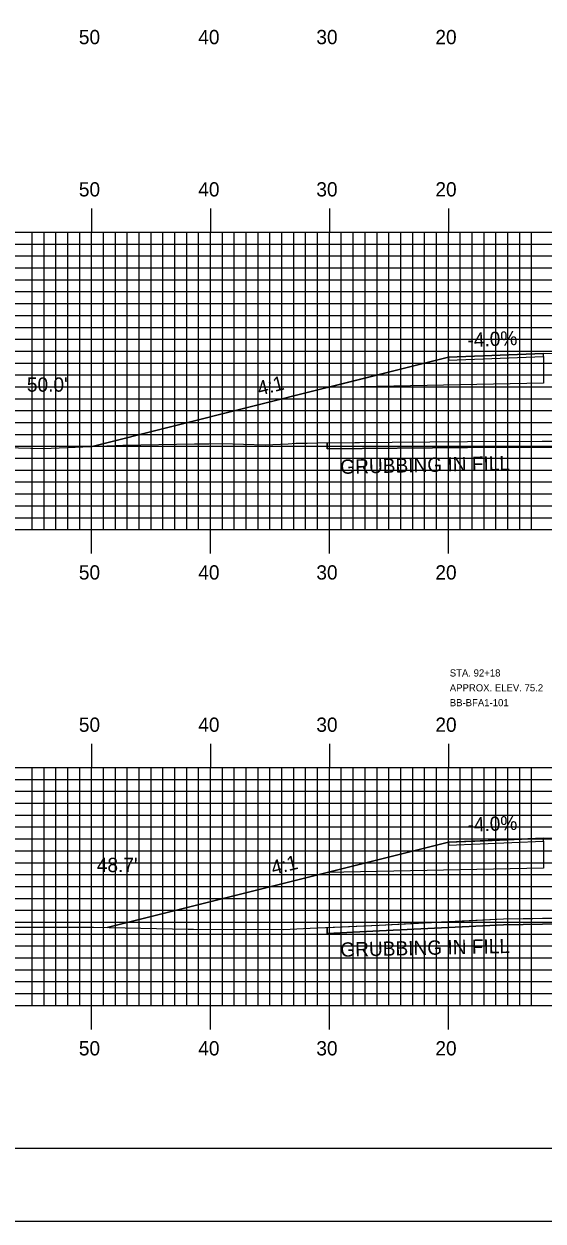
# Model space of a CAD drawing. Extents: x 1764939 to 1765282, y 442591 to 442811.
# Drawn here: x 1765049.2 to 1765092.8, y 442590.5 to 442691.2 of the extents above; entities that cross this region are included whole.
import ezdxf

# ---------------------------------------------------------------- set-up
doc = ezdxf.new("R2010")
doc.units = 0
for name, color, linetype in [('ANNOTATION', 7, 'Continuous'), ('BORDER', 7, 'Continuous'), ('D_Roadway_Centerline', 7, 'Continuous'), ('D_Roadway_Edge_Shoulder', 7, 'Continuous'), ('D_Roadway_SlopeLines', 7, 'Continuous'), ('D_Roadway_SubGrade', 7, 'Continuous'), ('D_Text_Standard', 7, 'Continuous'), ('GRUBBING IN FILL', 7, 'Continuous'), ('H_V ANNOTATION', 7, 'Continuous'), ('MAJOR', 7, 'Continuous'), ('MINOR', 7, 'Continuous'), ('PLOT BOUNDARY', 7, 'Continuous'), ('ROCKS', 7, 'Continuous'), ('S_Roadway_Centerline', 7, 'Continuous')]:
    doc.layers.add(name, color=color, linetype=linetype)

msp = doc.modelspace()

# ---------------------------------------------------------------- linework, layer by layer
at = {"layer": 'BORDER'}
msp.add_lwpolyline([(1764955.26, 442596.67), (1765275.26, 442596.67), (1765275.26, 442806.67), (1764955.26, 442806.67)], close=True, dxfattribs=at)
at = {"layer": 'D_Roadway_Centerline'}
for points in [[(1765054.9, 442655.66), (1765074.68, 442660.6), (1765074.68, 442660.6), (1765074.69, 442660.6), (1765084.86, 442663.15), (1765092.86, 442663.47), (1765092.86, 442663.47), (1765098.25, 442663.57), (1765104.85, 442663.71), (1765104.86, 442663.71), (1765116.85, 442663.47), (1765116.86, 442663.47), (1765116.86, 442663.47), (1765124.86, 442663.15), (1765124.86, 442663.15), (1765135.03, 442660.6), (1765136.03, 442660.35), (1765136.86, 442660.15), (1765151.59, 442656.46), (1765151.59, 442656.46)], [(1765056.16, 442615.22), (1765056.16, 442615.22), (1765074.68, 442619.85), (1765074.69, 442619.85), (1765079.22, 442620.99), (1765084.86, 442622.4), (1765084.86, 442622.4), (1765088.54, 442622.54), (1765092.86, 442622.72), (1765092.86, 442622.72), (1765104.86, 442622.96), (1765104.86, 442622.96), (1765116.86, 442622.72), (1765116.86, 442622.72), (1765122.81, 442622.48), (1765124.86, 442622.4), (1765124.86, 442622.4), (1765135.03, 442619.85), (1765135.03, 442619.85), (1765136.86, 442619.4), (1765136.86, 442619.4), (1765148.63, 442616.45)]]:
    msp.add_lwpolyline(points, dxfattribs=at)
at = {"layer": 'D_Roadway_Edge_Shoulder'}
for points in [[(1765092.86, 442663.47), (1765084.86, 442663.15), (1765084.86, 442662.9), (1765092.86, 442663.22)], [(1765092.86, 442622.72), (1765084.86, 442622.4), (1765084.86, 442622.15), (1765092.86, 442622.47)]]:
    msp.add_lwpolyline(points, close=True, dxfattribs=at)
at = {"layer": 'D_Roadway_SlopeLines'}
for points in [[(1765084.86, 442663.15), (1765074.68, 442660.6), (1765054.9, 442655.66)], [(1765084.86, 442622.4), (1765074.68, 442619.85), (1765056.16, 442615.22)]]:
    msp.add_lwpolyline(points, dxfattribs=at)
at = {"layer": 'D_Roadway_SubGrade'}
for points in [[(1765084.86, 442662.9), (1765092.86, 442663.22), (1765092.86, 442662.8), (1765092.86, 442660.97), (1765074.68, 442660.6), (1765084.86, 442663.15)], [(1765084.86, 442622.15), (1765092.86, 442622.47), (1765092.86, 442622.05), (1765092.86, 442620.22), (1765074.68, 442619.85), (1765084.86, 442622.4)]]:
    msp.add_lwpolyline(points, close=True, dxfattribs=at)
at = {"layer": 'GRUBBING IN FILL'}
for p, q in [((1765074.68, 442655.95), (1765074.68, 442655.45)), ((1765074.68, 442615.23), (1765074.68, 442614.73))]:
    msp.add_line(p, q, dxfattribs=at)
for points in [[(1765074.68, 442655.45), (1765074.68, 442655.95), (1765080.14, 442656.01), (1765086.46, 442656.07), (1765092.75, 442656.09), (1765099.04, 442656.11), (1765104.86, 442656.13), (1765104.86, 442655.63), (1765101.88, 442655.62), (1765099.04, 442655.61), (1765092.75, 442655.59), (1765086.46, 442655.57), (1765080.57, 442655.51)], [(1765074.68, 442655.45), (1765074.68, 442655.95), (1765080.14, 442656.01), (1765086.46, 442656.07), (1765092.75, 442656.09), (1765099.04, 442656.11), (1765104.86, 442656.13), (1765104.86, 442655.63), (1765101.88, 442655.62), (1765099.04, 442655.61), (1765092.75, 442655.59), (1765086.46, 442655.57), (1765080.57, 442655.51)], [(1765074.68, 442615.23), (1765079.04, 442615.43), (1765084.27, 442615.69), (1765089.49, 442615.94), (1765094.43, 442616.02), (1765099.36, 442616.11), (1765104, 442616.29), (1765104.86, 442616.32), (1765104.86, 442615.82), (1765104.01, 442615.79), (1765099.37, 442615.61), (1765094.44, 442615.53), (1765089.51, 442615.44), (1765084.29, 442615.19), (1765079.07, 442614.93), (1765074.68, 442614.73)], [(1765074.68, 442615.23), (1765079.04, 442615.43), (1765084.27, 442615.69), (1765089.49, 442615.94), (1765094.43, 442616.02), (1765099.36, 442616.11), (1765104, 442616.29), (1765104.86, 442616.32), (1765104.86, 442615.82), (1765104.01, 442615.79), (1765099.37, 442615.61), (1765094.44, 442615.53), (1765089.51, 442615.44), (1765084.29, 442615.19), (1765079.07, 442614.93), (1765074.68, 442614.73)]]:
    msp.add_lwpolyline(points, close=True, dxfattribs=at)
for points in [[(1765074.68, 442655.45), (1765086.46, 442655.57), (1765099.04, 442655.61), (1765104.73, 442655.63), (1765111.86, 442655.7), (1765122.5, 442655.9), (1765131.78, 442655.91), (1765135.03, 442655.92)], [(1765074.68, 442614.73), (1765079.07, 442614.93), (1765089.51, 442615.44), (1765099.37, 442615.61), (1765108.64, 442615.97), (1765120.32, 442615.98), (1765126.59, 442615.97), (1765127.71, 442615.97), (1765135.03, 442615.88)]]:
    msp.add_lwpolyline(points, dxfattribs=at)
at = {"layer": 'MAJOR'}
for p, q in [((1765054.86, 442675.67), (1765054.86, 442673.67)), ((1765064.86, 442675.67), (1765064.86, 442673.67)), ((1765074.86, 442675.67), (1765074.86, 442673.67)), ((1765084.86, 442675.67), (1765084.86, 442673.67)), ((1764964.86, 442673.67), (1765244.86, 442673.67)), ((1764964.86, 442673.67), (1765244.86, 442673.67)), ((1765054.86, 442648.67), (1765054.86, 442673.67)), ((1765064.86, 442648.67), (1765064.86, 442673.67)), ((1765074.86, 442648.67), (1765074.86, 442673.67)), ((1765084.86, 442648.67), (1765084.86, 442673.67)), ((1764964.86, 442668.67), (1765244.86, 442668.67)), ((1764964.86, 442663.67), (1765244.86, 442663.67)), ((1764964.86, 442658.67), (1765244.86, 442658.67)), ((1764964.86, 442653.67), (1765244.86, 442653.67)), ((1764964.86, 442648.67), (1765244.86, 442648.67)), ((1764964.86, 442648.67), (1765244.86, 442648.67)), ((1765054.86, 442646.66), (1765054.86, 442648.67)), ((1765064.86, 442646.66), (1765064.86, 442648.67)), ((1765074.86, 442646.66), (1765074.86, 442648.67)), ((1765084.86, 442646.66), (1765084.86, 442648.67)), ((1765054.86, 442630.67), (1765054.86, 442628.67)), ((1765064.86, 442630.67), (1765064.86, 442628.67)), ((1765074.86, 442630.67), (1765074.86, 442628.67)), ((1765084.86, 442630.67), (1765084.86, 442628.67)), ((1764964.86, 442628.67), (1765244.86, 442628.67)), ((1764964.86, 442628.67), (1765244.86, 442628.67)), ((1765054.86, 442608.67), (1765054.86, 442628.67)), ((1765064.86, 442608.67), (1765064.86, 442628.67)), ((1765074.86, 442608.67), (1765074.86, 442628.67)), ((1765084.86, 442608.67), (1765084.86, 442628.67)), ((1764964.86, 442623.67), (1765244.86, 442623.67)), ((1764964.86, 442618.67), (1765244.86, 442618.67)), ((1764964.86, 442613.67), (1765244.86, 442613.67)), ((1764964.86, 442608.67), (1765244.86, 442608.67)), ((1764964.86, 442608.67), (1765244.86, 442608.67)), ((1765054.86, 442606.66), (1765054.86, 442608.67)), ((1765064.86, 442606.66), (1765064.86, 442608.67)), ((1765074.86, 442606.66), (1765074.86, 442608.67)), ((1765084.86, 442606.66), (1765084.86, 442608.67))]:
    msp.add_line(p, q, dxfattribs=at)
at = {"layer": 'MINOR'}
for p, q in [((1765049.86, 442648.67), (1765049.86, 442673.67)), ((1765050.86, 442648.67), (1765050.86, 442673.67)), ((1765051.86, 442648.67), (1765051.86, 442673.67)), ((1765052.86, 442648.67), (1765052.86, 442673.67)), ((1765053.86, 442648.67), (1765053.86, 442673.67)), ((1765055.86, 442648.67), (1765055.86, 442673.67)), ((1765056.86, 442648.67), (1765056.86, 442673.67)), ((1765057.86, 442648.67), (1765057.86, 442673.67)), ((1765058.86, 442648.67), (1765058.86, 442673.67)), ((1765059.86, 442648.67), (1765059.86, 442673.67)), ((1765060.86, 442648.67), (1765060.86, 442673.67)), ((1765061.86, 442648.67), (1765061.86, 442673.67)), ((1765062.86, 442648.67), (1765062.86, 442673.67)), ((1765063.86, 442648.67), (1765063.86, 442673.67)), ((1765065.86, 442648.67), (1765065.86, 442673.67)), ((1765066.86, 442648.67), (1765066.86, 442673.67)), ((1765067.86, 442648.67), (1765067.86, 442673.67)), ((1765068.86, 442648.67), (1765068.86, 442673.67)), ((1765069.86, 442648.67), (1765069.86, 442673.67)), ((1765070.86, 442648.67), (1765070.86, 442673.67)), ((1765071.86, 442648.67), (1765071.86, 442673.67)), ((1765072.86, 442648.67), (1765072.86, 442673.67)), ((1765073.86, 442648.67), (1765073.86, 442673.67)), ((1765075.86, 442648.67), (1765075.86, 442673.67)), ((1765076.86, 442648.67), (1765076.86, 442673.67)), ((1765077.86, 442648.67), (1765077.86, 442673.67)), ((1765078.86, 442648.67), (1765078.86, 442673.67)), ((1765079.86, 442648.67), (1765079.86, 442673.67)), ((1765080.86, 442648.67), (1765080.86, 442673.67)), ((1765081.86, 442648.67), (1765081.86, 442673.67)), ((1765082.86, 442648.67), (1765082.86, 442673.67)), ((1765083.86, 442648.67), (1765083.86, 442673.67)), ((1765085.86, 442648.67), (1765085.86, 442673.67)), ((1765086.86, 442648.67), (1765086.86, 442673.67)), ((1765087.86, 442648.67), (1765087.86, 442673.67)), ((1765088.86, 442648.67), (1765088.86, 442673.67)), ((1765089.86, 442648.67), (1765089.86, 442673.67)), ((1765090.86, 442648.67), (1765090.86, 442673.67)), ((1765091.86, 442648.67), (1765091.86, 442673.67)), ((1764964.86, 442672.67), (1765244.86, 442672.67)), ((1764964.86, 442671.67), (1765244.86, 442671.67)), ((1764964.86, 442670.67), (1765244.86, 442670.67)), ((1764964.86, 442669.67), (1765244.86, 442669.67)), ((1764964.86, 442667.67), (1765244.86, 442667.67)), ((1764964.86, 442666.67), (1765244.86, 442666.67)), ((1764964.86, 442665.67), (1765244.86, 442665.67)), ((1764964.86, 442664.67), (1765244.86, 442664.67)), ((1764964.86, 442662.67), (1765244.86, 442662.67)), ((1764964.86, 442661.67), (1765244.86, 442661.67)), ((1764964.86, 442660.67), (1765244.86, 442660.67)), ((1764964.86, 442659.67), (1765244.86, 442659.67)), ((1764964.86, 442657.67), (1765244.86, 442657.67)), ((1764964.86, 442656.67), (1765244.86, 442656.67)), ((1764964.86, 442655.67), (1765244.86, 442655.67)), ((1764964.86, 442654.67), (1765244.86, 442654.67)), ((1764964.86, 442652.67), (1765244.86, 442652.67)), ((1764964.86, 442651.67), (1765244.86, 442651.67)), ((1764964.86, 442650.67), (1765244.86, 442650.67)), ((1764964.86, 442649.67), (1765244.86, 442649.67)), ((1765049.86, 442608.67), (1765049.86, 442628.67)), ((1765050.86, 442608.67), (1765050.86, 442628.67)), ((1765051.86, 442608.67), (1765051.86, 442628.67)), ((1765052.86, 442608.67), (1765052.86, 442628.67)), ((1765053.86, 442608.67), (1765053.86, 442628.67)), ((1765055.86, 442608.67), (1765055.86, 442628.67)), ((1765056.86, 442608.67), (1765056.86, 442628.67)), ((1765057.86, 442608.67), (1765057.86, 442628.67)), ((1765058.86, 442608.67), (1765058.86, 442628.67)), ((1765059.86, 442608.67), (1765059.86, 442628.67)), ((1765060.86, 442608.67), (1765060.86, 442628.67)), ((1765061.86, 442608.67), (1765061.86, 442628.67)), ((1765062.86, 442608.67), (1765062.86, 442628.67)), ((1765063.86, 442608.67), (1765063.86, 442628.67)), ((1765065.86, 442608.67), (1765065.86, 442628.67)), ((1765066.86, 442608.67), (1765066.86, 442628.67)), ((1765067.86, 442608.67), (1765067.86, 442628.67)), ((1765068.86, 442608.67), (1765068.86, 442628.67)), ((1765069.86, 442608.67), (1765069.86, 442628.67)), ((1765070.86, 442608.67), (1765070.86, 442628.67)), ((1765071.86, 442608.67), (1765071.86, 442628.67)), ((1765072.86, 442608.67), (1765072.86, 442628.67)), ((1765073.86, 442608.67), (1765073.86, 442628.67)), ((1765075.86, 442608.67), (1765075.86, 442628.67)), ((1765076.86, 442608.67), (1765076.86, 442628.67)), ((1765077.86, 442608.67), (1765077.86, 442628.67)), ((1765078.86, 442608.67), (1765078.86, 442628.67)), ((1765079.86, 442608.67), (1765079.86, 442628.67)), ((1765080.86, 442608.67), (1765080.86, 442628.67)), ((1765081.86, 442608.67), (1765081.86, 442628.67)), ((1765082.86, 442608.67), (1765082.86, 442628.67)), ((1765083.86, 442608.67), (1765083.86, 442628.67)), ((1765085.86, 442608.67), (1765085.86, 442628.67)), ((1765086.86, 442608.67), (1765086.86, 442628.67)), ((1765087.86, 442608.67), (1765087.86, 442628.67)), ((1765088.86, 442608.67), (1765088.86, 442628.67)), ((1765089.86, 442608.67), (1765089.86, 442628.67)), ((1765090.86, 442608.67), (1765090.86, 442628.67)), ((1765091.86, 442608.67), (1765091.86, 442628.67)), ((1764964.86, 442627.67), (1765244.86, 442627.67)), ((1764964.86, 442626.67), (1765244.86, 442626.67)), ((1764964.86, 442625.67), (1765244.86, 442625.67)), ((1764964.86, 442624.67), (1765244.86, 442624.67)), ((1764964.86, 442622.67), (1765244.86, 442622.67)), ((1764964.86, 442621.67), (1765244.86, 442621.67)), ((1764964.86, 442620.67), (1765244.86, 442620.67)), ((1764964.86, 442619.67), (1765244.86, 442619.67)), ((1764964.86, 442617.67), (1765244.86, 442617.67)), ((1764964.86, 442616.67), (1765244.86, 442616.67)), ((1764964.86, 442615.67), (1765244.86, 442615.67)), ((1764964.86, 442614.67), (1765244.86, 442614.67)), ((1764964.86, 442612.67), (1765244.86, 442612.67)), ((1764964.86, 442611.67), (1765244.86, 442611.67)), ((1764964.86, 442610.67), (1765244.86, 442610.67)), ((1764964.86, 442609.67), (1765244.86, 442609.67))]:
    msp.add_line(p, q, dxfattribs=at)
at = {"layer": 'PLOT BOUNDARY'}
msp.add_lwpolyline([(1764939.07, 442590.55), (1765279.07, 442590.55), (1765279.07, 442810.55), (1764939.07, 442810.55)], close=True, dxfattribs=at)
at = {"layer": 'S_Roadway_Centerline'}
for points in [[(1765044.58, 442655.65), (1765050.78, 442655.49), (1765057.5, 442655.76), (1765063.5, 442655.87), (1765064.18, 442655.87), (1765064.71, 442655.87), (1765065.82, 442655.9), (1765069.45, 442655.8), (1765071.4, 442655.88), (1765072.03, 442655.94), (1765072.73, 442655.94), (1765072.9, 442655.94), (1765073, 442655.93), (1765073.82, 442655.95), (1765086.46, 442656.07), (1765099.04, 442656.11)], [(1765038.72, 442615.25), (1765055.02, 442615.24), (1765062.98, 442615.09), (1765063.05, 442615.09), (1765063.43, 442615.09), (1765070.99, 442615.05), (1765073.24, 442615.16), (1765079.04, 442615.43), (1765089.49, 442615.94), (1765099.36, 442616.11), (1765108.63, 442616.47), (1765120.32, 442616.48), (1765126.59, 442616.47), (1765127.71, 442616.47), (1765131.71, 442616.42), (1765144.25, 442616.38), (1765149.43, 442616.47), (1765161.88, 442616.23)]]:
    msp.add_lwpolyline(points, dxfattribs=at)

# ---------------------------------------------------------------- texts
at = {"layer": 'ANNOTATION'}
for s, rotation, p in [('-4.0%', 2.2905, (1765086.49, 442664.01)), ('4:1', 14.0394, (1765068.97, 442659.92)), ('-4.0%', 2.2908, (1765086.49, 442623.26)), ('4:1', 14.0382, (1765070.13, 442619.63))]:
    msp.add_text(s, height=1.2, rotation=rotation, dxfattribs=at).set_placement(p)
at = {"layer": 'D_Text_Standard'}
for s, p in [("50.0'", (1765049.42, 442660.26)), ("48.7'", (1765055.3, 442619.88))]:
    msp.add_text(s, height=1.2, dxfattribs=at).set_placement(p)
at = {"layer": 'GRUBBING IN FILL'}
for p in [(1765075.79, 442653.35), (1765075.79, 442612.76)]:
    msp.add_text('GRUBBING IN FILL', height=1.2, rotation=1.2837, dxfattribs=at).set_placement(p)
at = {"layer": 'H_V ANNOTATION'}
for s, p in [('50', (1765053.79, 442689.47)), ('40', (1765063.83, 442689.47)), ('30', (1765073.76, 442689.47)), ('20', (1765083.77, 442689.47)), ('50', (1765053.79, 442676.67)), ('40', (1765063.83, 442676.67)), ('30', (1765073.76, 442676.67)), ('20', (1765083.77, 442676.67)), ('50', (1765053.79, 442644.47)), ('40', (1765063.83, 442644.47)), ('30', (1765073.76, 442644.47)), ('20', (1765083.77, 442644.47)), ('50', (1765053.79, 442631.67)), ('40', (1765063.83, 442631.67)), ('30', (1765073.76, 442631.67)), ('20', (1765083.77, 442631.67)), ('50', (1765053.79, 442604.47)), ('40', (1765063.83, 442604.47)), ('30', (1765073.76, 442604.47)), ('20', (1765083.77, 442604.47))]:
    msp.add_text(s, height=1.2, dxfattribs=at).set_placement(p)
at = {"layer": 'ROCKS'}
for s, p in [('STA. 92+18', (1765084.98, 442636.32)), ('APPROX. ELEV. 75.2', (1765084.98, 442635.07)), ('BB-BFA1-101', (1765084.98, 442633.82))]:
    msp.add_text(s, height=0.6, rotation=360, dxfattribs=at).set_placement(p)

doc.saveas('drawing.dxf')
